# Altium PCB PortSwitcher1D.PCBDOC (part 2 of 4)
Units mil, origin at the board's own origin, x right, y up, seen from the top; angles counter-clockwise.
Board outline 6005.03 x 6005.03 mil, 4 copper layers (Top Layer, InternalPlane1, InternalPlane2, Bottom Layer); 153 components, 325 nets, 1175 pads, 173 vias.
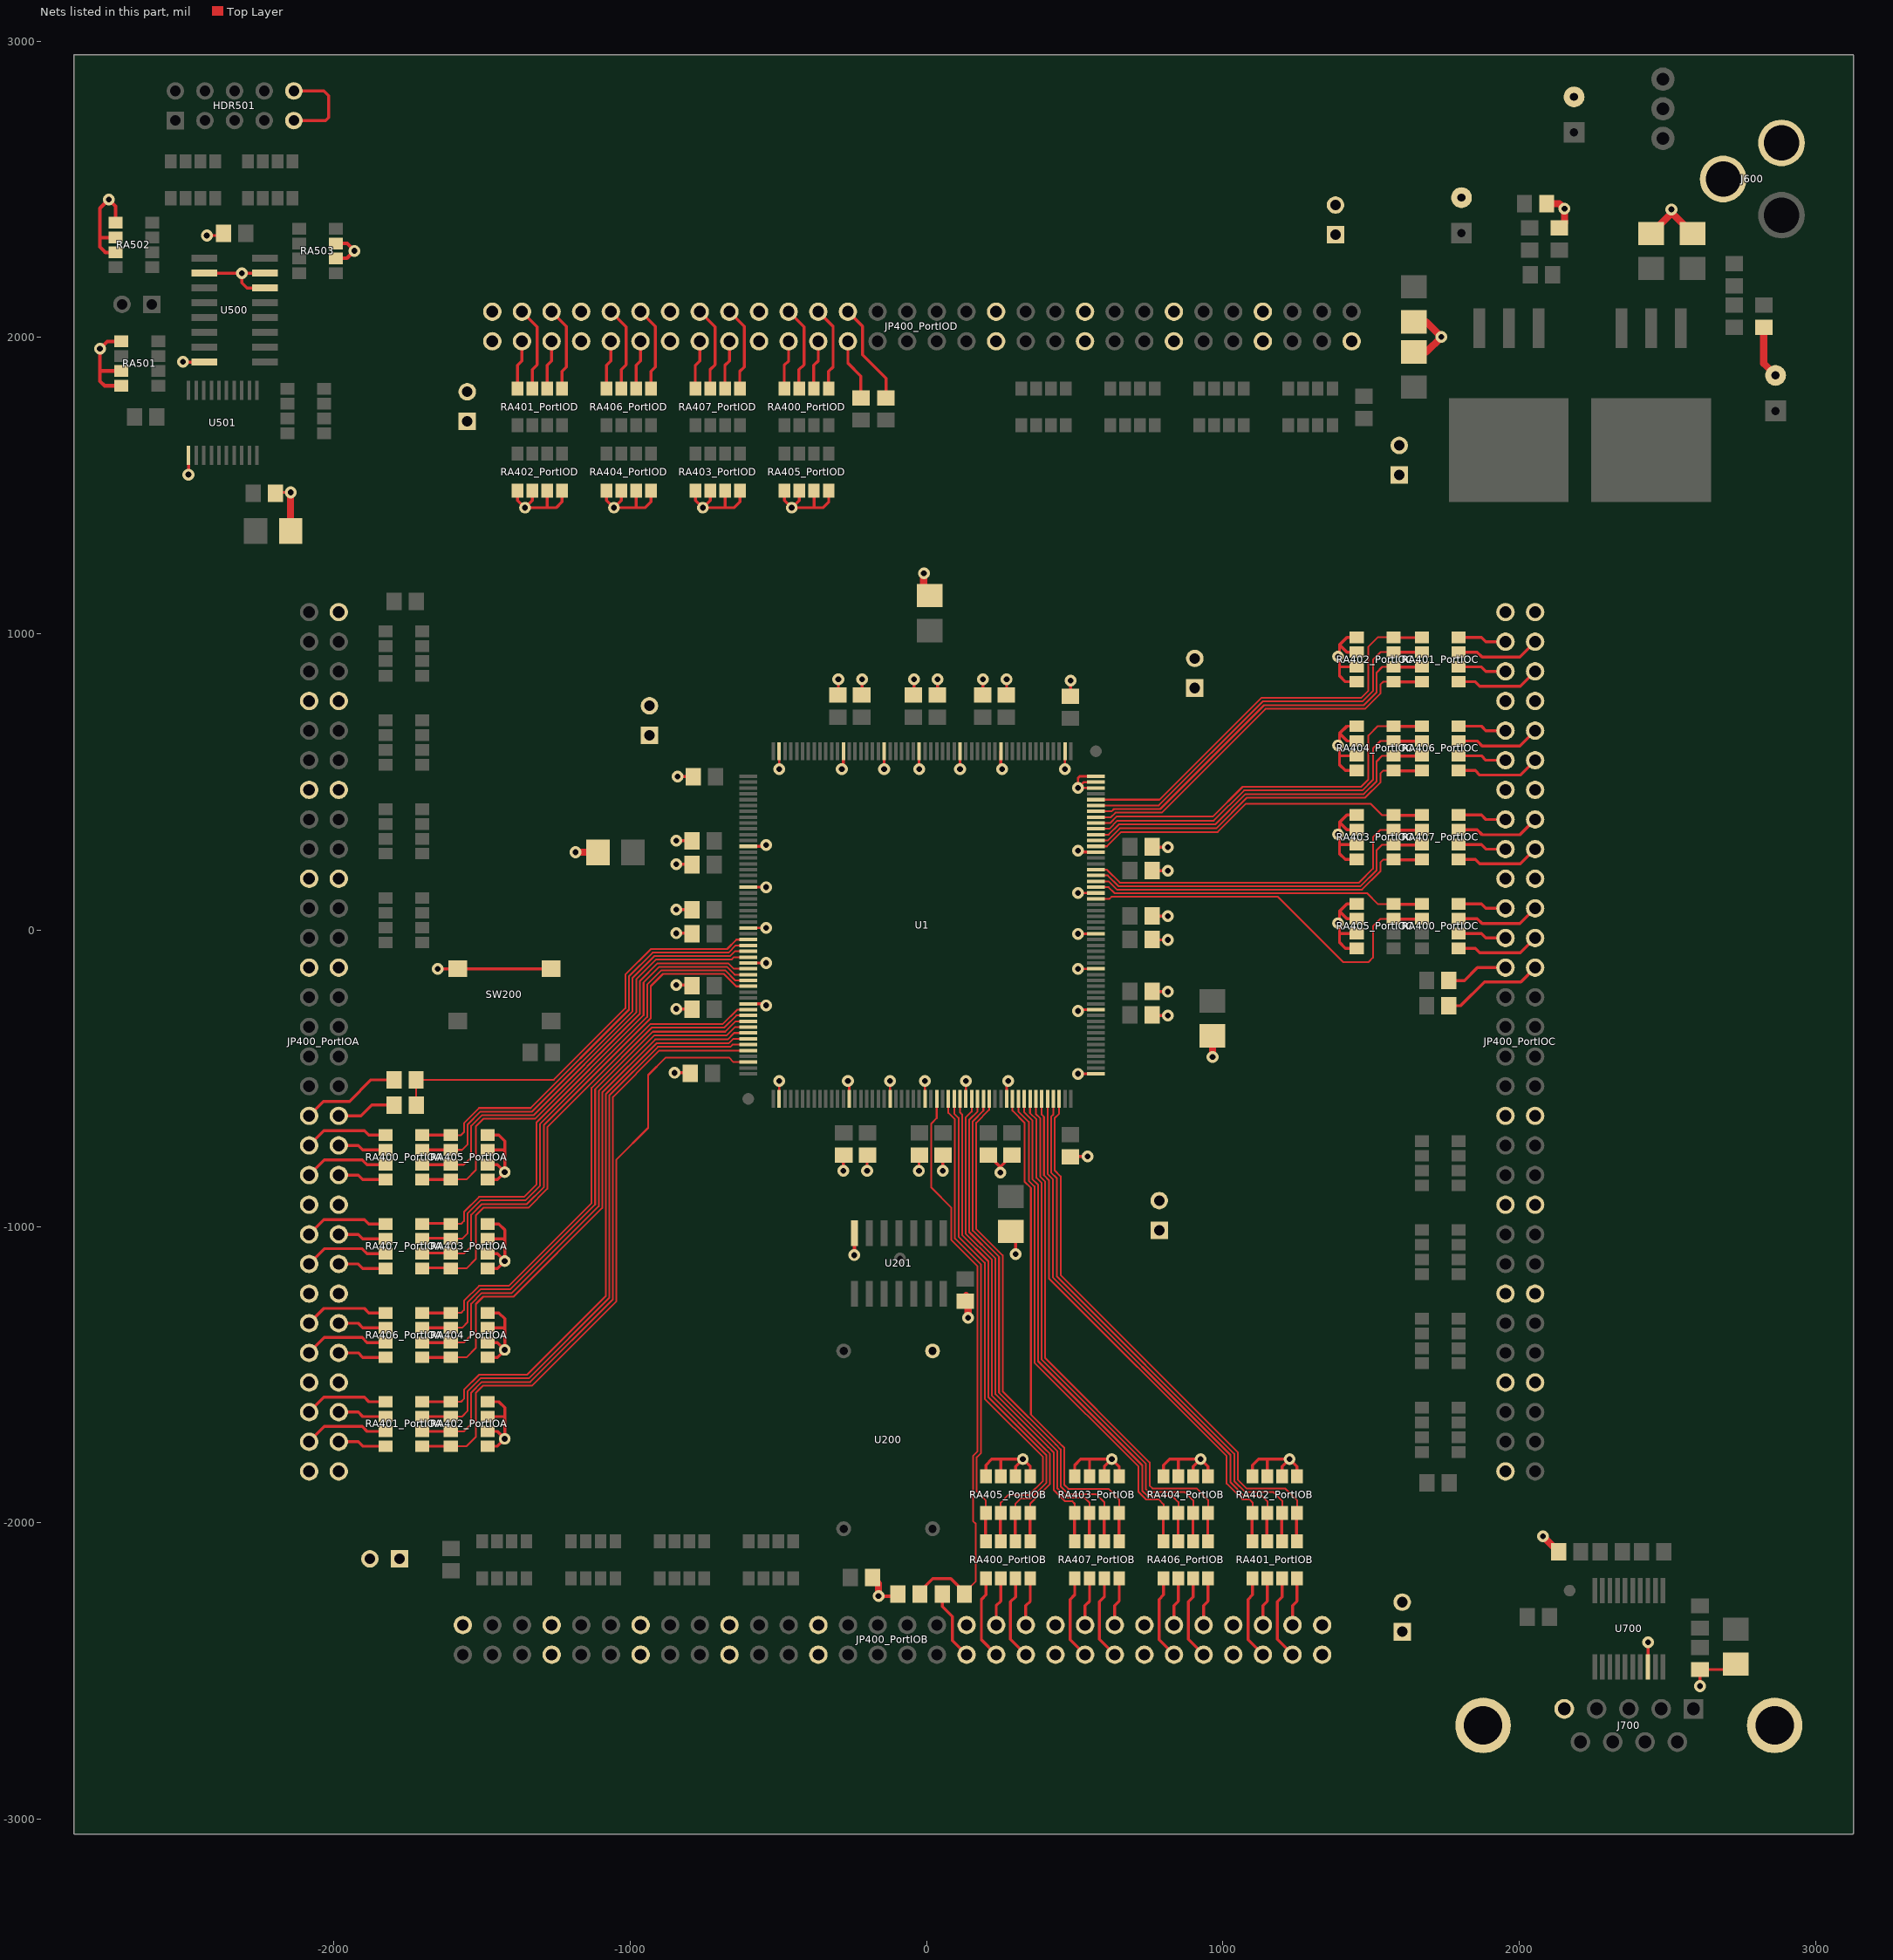
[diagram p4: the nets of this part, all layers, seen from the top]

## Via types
v1: diameter 40, hole 19.68, Top Layer to Bottom Layer, 173 vias

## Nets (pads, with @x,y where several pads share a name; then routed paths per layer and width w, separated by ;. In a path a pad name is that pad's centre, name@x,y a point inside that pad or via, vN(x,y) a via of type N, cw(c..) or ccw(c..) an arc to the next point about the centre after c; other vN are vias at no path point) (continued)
GND: C200.2 C201.2 C202.2 C203.2 C204.2 C205.2 C206.2 C207.2 C208.1 C209.1 C210.1 C211.1 C212.1 C213.1 C214.1 C215.1 C216.2 C217.2 C218.2 C219.2 C220.2 C221.2 C222.1 C223.1 C224.1 C225.1 C226.1 C227.1 C228.2 C229.2 C230.2 C231.2 C232.2 C233.2 C500.2 C501.2 C502.2 C600.2 C601.2 C602.2 C603.2 C604.2 C605.2 C606.2 C703.2 C704.2 C705.2 HDR501.9 HDR501.10 HDR600.1 HDR600.2 HDR601.1 HDR601.2 HDR602.1 HDR602.2 HDR603.1 HDR603.2 HDR604.1 HDR604.2 HDR605.1 HDR605.2 HDR606.1 HDR606.2 HDR607.1 HDR607.2 J600.2 J600.3 J700.5 J700.10 J700.11 JP400_PortIOA.1 JP400_PortIOA.2 JP400_PortIOA.7 JP400_PortIOA.8 JP400_PortIOA.13 JP400_PortIOA.14 JP400_PortIOA.19 JP400_PortIOA.20 JP400_PortIOA.26 JP400_PortIOA.35 JP400_PortIOA.36 JP400_PortIOA.41 JP400_PortIOA.42 JP400_PortIOA.47 JP400_PortIOA.48 JP400_PortIOA.53 JP400_PortIOA.54 JP400_PortIOA.60 JP400_PortIOB.1 JP400_PortIOB.2 JP400_PortIOB.7 JP400_PortIOB.8 JP400_PortIOB.13 JP400_PortIOB.14 JP400_PortIOB.19 JP400_PortIOB.20 JP400_PortIOB.26 JP400_PortIOB.35 JP400_PortIOB.36 JP400_PortIOB.41 JP400_PortIOB.42 JP400_PortIOB.47 JP400_PortIOB.48 JP400_PortIOB.53 JP400_PortIOB.54 JP400_PortIOB.60 JP400_PortIOC.1 JP400_PortIOC.2 JP400_PortIOC.7 JP400_PortIOC.8 JP400_PortIOC.13 JP400_PortIOC.14 JP400_PortIOC.19 JP400_PortIOC.20 JP400_PortIOC.26 JP400_PortIOC.35 JP400_PortIOC.36 JP400_PortIOC.41 JP400_PortIOC.42 JP400_PortIOC.47 JP400_PortIOC.48 JP400_PortIOC.53 JP400_PortIOC.54 JP400_PortIOC.60 JP400_PortIOD.1 JP400_PortIOD.2 JP400_PortIOD.7 JP400_PortIOD.8 JP400_PortIOD.13 JP400_PortIOD.14 JP400_PortIOD.19 JP400_PortIOD.20 JP400_PortIOD.26 JP400_PortIOD.35 JP400_PortIOD.36 JP400_PortIOD.41 JP400_PortIOD.42 JP400_PortIOD.47 JP400_PortIOD.48 JP400_PortIOD.53 JP400_PortIOD.54 JP400_PortIOD.60 pad.GND R401_PortIOA.1 R401_PortIOB.1 R401_PortIOC.1 R401_PortIOD.1 R603.1 R605.1 R606.1 RA402_PortIOA.1 RA402_PortIOA.2 RA402_PortIOA.3 RA402_PortIOA.4 RA402_PortIOB.1 RA402_PortIOB.2 RA402_PortIOB.3 RA402_PortIOB.4 RA402_PortIOC.1 RA402_PortIOC.2 RA402_PortIOC.3 RA402_PortIOC.4 RA402_PortIOD.1 RA402_PortIOD.2 RA402_PortIOD.3 RA402_PortIOD.4 RA403_PortIOA.1 RA403_PortIOA.2 RA403_PortIOA.3 RA403_PortIOA.4 RA403_PortIOB.1 RA403_PortIOB.2 RA403_PortIOB.3 RA403_PortIOB.4 RA403_PortIOC.1 RA403_PortIOC.2 RA403_PortIOC.3 RA403_PortIOC.4 RA403_PortIOD.1 RA403_PortIOD.2 RA403_PortIOD.3 RA403_PortIOD.4 RA404_PortIOA.1 RA404_PortIOA.2 RA404_PortIOA.3 RA404_PortIOA.4 RA404_PortIOB.1 RA404_PortIOB.2 RA404_PortIOB.3 RA404_PortIOB.4 RA404_PortIOC.1 RA404_PortIOC.2 RA404_PortIOC.3 RA404_PortIOC.4 RA404_PortIOD.1 RA404_PortIOD.2 RA404_PortIOD.3 RA404_PortIOD.4 RA405_PortIOA.1 RA405_PortIOA.2 RA405_PortIOA.3 RA405_PortIOA.4 RA405_PortIOB.1 RA405_PortIOB.2 RA405_PortIOB.3 RA405_PortIOB.4 RA405_PortIOC.1 RA405_PortIOC.2 RA405_PortIOC.3 RA405_PortIOC.4 RA405_PortIOD.1 RA405_PortIOD.2 RA405_PortIOD.3 RA405_PortIOD.4 RA501.5 RA501.7 RA501.8 RA502.5 RA502.6 RA502.7 RA503.6 RA503.7 SW200.3 SW200.4 U1.1 U1.12 U1.19 U1.25 U1.32 U1.39 U1.50 U1.51 U1.52 U1.54 U1.65 U1.72 U1.79 U1.85 U1.92 U1.103 U1.117 U1.124 U1.131 U1.137 U1.144 U1.158 U1.170 U1.177 U1.183 U1.190 U1.197 U200.7 U201.7 U500.2 U500.8 U500.14 U500.15 U501.11 U700.18 | length 20269.8
  Top Layer w8: v1(467.02,543.39) U1.54@467.02,603.91 ; 518.74,519.26 516.7,519.26 ; U1.50@571.35,479.89 v1(510.84,479.89) ; U1.51@571.35,499.58 530.52,499.58 ; U1.52@571.35,519.26 516.7,519.26 ; v1(510.84,479.89) 523.49,492.54 530.52,499.58 ; v1(510.84,479.89) 530.52,499.58 ; v1(510.84,479.89) 510.84,513.39 516.7,519.26 ; U1.137@-601.88,-110.66 v1(-541.37,-110.66) U1.137@-601.88,-110.66 ; U1.131@-601.88,7.45 v1(-541.37,7.45) U1.131@-601.88,7.45 ; U1.124@-601.88,145.24 v1(-541.37,145.24) U1.124@-601.88,145.24 ; U1.158@-497.55,-569.32 v1(-497.55,-508.81) U1.158@-497.55,-569.32 ; U1.103@-497.55,603.91 v1(-497.39,543.45) U1.103@-497.55,603.91 ; v1(-143.39,543.45) U1.85@-143.22,603.91 v1(-143.39,543.45) ; U1.177@-123.53,-569.32 v1(-123.53,-508.81) U1.177@-123.53,-569.32 ; v1(-25.39,543.45) U1.79@-25.11,603.91 v1(-25.39,543.45) ; U1.183@-5.42,-569.32 v1(-5.42,-508.81) U1.183@-5.42,-569.32 ; v1(112.69,543.39) U1.72@112.69,603.91 v1(112.69,543.39) ; U1.190@132.37,-569.32 v1(132.37,-508.81) U1.190@132.37,-569.32 ; v1(510.84,-484.68) U1.1@571.35,-484.68 v1(510.84,-484.68) ; v1(510.84,-130.35) U1.19@571.35,-130.35 v1(510.84,-130.35) ; v1(510.84,-12.24) U1.25@571.35,-12.24 v1(510.84,-12.24) ; v1(510.84,125.56) U1.32@571.35,125.56 v1(510.84,125.56)
  Top Layer w10: v1(-2509.7,1918.38) -2508.62,1917.29 U500.8@-2437.63,1917.29 ; v1(-2491.01,1537.57) -2490.42,1538.16 U501.11@-2490.42,1603.04 ; U500.2@-2437.63,2217.29 U500.15@-2232.9,2217.29 ; v1(-2429.02,2344.45) -2380.51,2344.45 C501.2@-2372.67,2352.29 ; v1(-2310.94,2217.29) -2310.94,2185.04 -2293.18,2167.29 U500.14@-2232.9,2167.29 ; C500.2@-2195.4,1477.55 v1(-2145.62,1477.55) ; HDR501.9@-2135.26,2732.29 -2028.38,2732.29 -2017.7,2742.97 -2017.7,2815.79 -2034.21,2832.29 HDR501.10@-2135.26,2832.29 ; JP400_PortIOA.26@-1983.77,-626.41 -1908.56,-626.41 -1872.15,-590 R401_PortIOA.1@-1797.4,-590 ; v1(-1649.69,-130.31) -1268.18,-130.31 SW200.3@-1267.39,-129.52 ; v1(-850.34,-481.44) C208.1@-798.93,-481.44 ; v1(-844.34,-265.44) C213.1@-792.93,-265.44 ; v1(-844.34,-185.44) C226.1@-792.93,-185.44 ; v1(-844.34,-10.44) C212.1@-792.93,-10.44 ; v1(-844.34,69.56) C225.1@-792.93,69.56 ; v1(-844.34,222.56) C221.2@-792.93,222.56 ; v1(-844.34,302.56) C207.2@-792.93,302.56 ; v1(-840.34,518.56) C204.2@-788.93,518.56 ; C201.2@-298,794.96 v1(-298,846.37) ; v1(-280.85,-811.79) C206.2@-280.85,-760.38 ; JP400_PortIOD.26@-265.66,1987.37 -265.66,1913.86 -222.07,1870.27 R401_PortIOD.1@-222.07,1796.53 ; C220.2@-218,794.96 v1(-218,846.37) ; v1(-200.85,-811.79) C218.2@-200.85,-760.38 ; C200.2@-43,794.96 v1(-43,846.37) ; v1(-25.85,-811.79) C211.1@-25.85,-760.38 ; C219.2@37,794.96 v1(37,846.37) ; v1(54.15,-811.79) C227.1@54.15,-760.38 ; C224.1@190,794.96 v1(190,846.37) ; C217.2@208.42,-759.11 v1@248.78,-799.46 ; v1(248.78,-817.53) 248.78,-798.76 C214.1@288.42,-759.11 ; C203.2@270,794.96 v1(270,846.37) ; C231.2@284.74,-1016.76 300.68,-1032.71 v1(300.68,-1092.94) ; C215.1@484.74,-765.11 486.63,-763.22 v1(542.81,-763.22) ; C202.2@486,790.96 v1(486,842.37) ; C205.2@762.41,-287.66 v1(813.82,-287.66) ; C216.2@762.41,-207.66 v1(813.82,-207.66) ; C210.1@762.41,-32.66 v1(813.82,-32.66) ; C222.1@762.41,47.34 v1(813.82,47.34) ; C223.1@762.41,200.34 v1(813.82,200.34) ; C209.1@762.41,280.34 v1(813.82,280.34) ; R401_PortIOC.1@1762.4,-170 1814.73,-170 1858.32,-126.41 JP400_PortIOC.26@1953.24,-126.41 ; U700.18@2434.9,-2485.46 v1(2434.9,-2403.35) ; v1@2609.74,-2550.64 C704.2@2609.74,-2495.11 2711.39,-2495.11 C705.2@2729.74,-2476.76 ; -1448.77,-1741.41 RA402_PortIOA.1@-1481.77,-1741.41 -1448.77,-1741.41 ; -1448.77,-1741.41 pad.GND@-1423.77,-1716.41 ; -1448.77,-1741.41 pad.GND@-1423.77,-1716.41 ; -1448.77,-1691.41 RA402_PortIOA.2@-1481.77,-1691.41 -1448.77,-1691.41 ; -1448.77,-1691.41 pad.GND@-1423.77,-1716.41 ; -1448.77,-1691.41 pad.GND@-1423.77,-1716.41 ; -1448.77,-1441.41 RA404_PortIOA.1@-1481.77,-1441.41 -1448.77,-1441.41 ; -1448.77,-1441.41 pad.GND@-1423.77,-1416.41 ; -1448.77,-1441.41 pad.GND@-1423.77,-1416.41 ; -1448.77,-1391.41 pad.GND@-1423.77,-1416.41 ; -1448.77,-1391.41 RA404_PortIOA.2@-1481.77,-1391.41 -1448.77,-1391.41 ; -1448.77,-1391.41 pad.GND@-1423.77,-1416.41 ; -1448.77,-1141.41 RA403_PortIOA.1@-1481.77,-1141.41 -1448.77,-1141.41 ; -1448.77,-1141.41 pad.GND@-1423.77,-1116.41 ; -1448.77,-1141.41 pad.GND@-1423.77,-1116.41 ; -1448.77,-1091.41 RA403_PortIOA.2@-1481.77,-1091.41 -1448.77,-1091.41 ; -1448.77,-1091.41 pad.GND@-1423.77,-1116.41 ; -1448.77,-1091.41 pad.GND@-1423.77,-1116.41 ; -1448.77,-841.41 RA405_PortIOA.1@-1481.77,-841.41 -1448.77,-841.41 ; -1448.77,-841.41 pad.GND@-1423.77,-816.41 ; -1448.77,-841.41 pad.GND@-1423.77,-816.41 ; -1448.77,-791.41 RA405_PortIOA.2@-1481.77,-791.41 -1448.77,-791.41 ; -1448.77,-791.41 pad.GND@-1423.77,-816.41 ; -1448.77,-791.41 pad.GND@-1423.77,-816.41 ; -1443.77,-1591.41 -1423.77,-1611.41 ; -1443.77,-1591.41 RA402_PortIOA.4@-1481.77,-1591.41 -1443.77,-1591.41 ; -1443.77,-1291.41 -1423.77,-1311.41 ; -1443.77,-1291.41 RA404_PortIOA.4@-1481.77,-1291.41 -1443.77,-1291.41 ; -1443.77,-991.41 -1423.77,-1011.41 ; -1443.77,-991.41 RA403_PortIOA.4@-1481.77,-991.41 -1443.77,-991.41 ; -1443.77,-691.41 -1423.77,-711.41 ; -1443.77,-691.41 RA405_PortIOA.4@-1481.77,-691.41 -1443.77,-691.41 ; pad.GND@-1423.77,-1716.41 -1423.77,-1641.41 ; pad.GND@-1423.77,-1716.41 -1423.77,-1641.41 ; -1423.77,-1641.41 RA402_PortIOA.3@-1481.77,-1641.41 -1423.77,-1641.41 ; -1423.77,-1641.41 -1423.77,-1611.41 ; -1423.77,-1641.41 -1423.77,-1611.41 ; pad.GND@-1423.77,-1416.41 -1423.77,-1341.41 ; pad.GND@-1423.77,-1416.41 -1423.77,-1341.41 ; -1423.77,-1341.41 -1423.77,-1311.41 ; -1423.77,-1341.41 RA404_PortIOA.3@-1481.77,-1341.41 -1423.77,-1341.41 ; -1423.77,-1341.41 -1423.77,-1311.41 ; pad.GND@-1423.77,-1116.41 -1423.77,-1041.41 ; pad.GND@-1423.77,-1116.41 -1423.77,-1041.41 ; -1423.77,-1041.41 RA403_PortIOA.3@-1481.77,-1041.41 -1423.77,-1041.41 ; -1423.77,-1041.41 -1423.77,-1011.41 ; -1423.77,-1041.41 -1423.77,-1011.41 ; pad.GND@-1423.77,-816.41 -1423.77,-741.41 ; pad.GND@-1423.77,-816.41 -1423.77,-741.41 ; -1423.77,-741.41 RA405_PortIOA.3@-1481.77,-741.41 -1423.77,-741.41 ; -1423.77,-741.41 -1423.77,-711.41 ; -1423.77,-741.41 -1423.77,-711.41 ; -1380.26,1450.8 pad.GND@-1355.26,1425.8 ; -1380.26,1450.8 RA402_PortIOD.1@-1380.26,1483.8 -1380.26,1450.8 ; -1380.26,1450.8 pad.GND@-1355.26,1425.8 ; pad.GND@-1355.26,1425.8 -1280.26,1425.8 ; pad.GND@-1355.26,1425.8 -1330.26,1450.8 ; pad.GND@-1355.26,1425.8 -1330.26,1450.8 ; pad.GND@-1355.26,1425.8 -1280.26,1425.8 ; -1330.26,1450.8 RA402_PortIOD.2@-1330.26,1483.8 -1330.26,1450.8 ; -1280.26,1425.8 -1250.26,1425.8 ; -1280.26,1425.8 RA402_PortIOD.3@-1280.26,1483.8 -1280.26,1425.8 ; -1280.26,1425.8 -1250.26,1425.8 ; -1250.26,1425.8 -1230.26,1445.8 ; -1230.26,1445.8 RA402_PortIOD.4@-1230.26,1483.8 -1230.26,1445.8 ; -1080.26,1450.8 RA404_PortIOD.1@-1080.26,1483.8 -1080.26,1450.8 ; -1080.26,1450.8 pad.GND@-1055.26,1425.8 ; -1080.26,1450.8 pad.GND@-1055.26,1425.8 ; pad.GND@-1055.26,1425.8 -980.26,1425.8 ; pad.GND@-1055.26,1425.8 -1030.26,1450.8 ; pad.GND@-1055.26,1425.8 -1030.26,1450.8 ; pad.GND@-1055.26,1425.8 -980.26,1425.8 ; -1030.26,1450.8 RA404_PortIOD.2@-1030.26,1483.8 -1030.26,1450.8 ; -980.26,1425.8 -950.26,1425.8 ; -980.26,1425.8 RA404_PortIOD.3@-980.26,1483.8 -980.26,1425.8 ; -980.26,1425.8 -950.26,1425.8 ; -950.26,1425.8 -930.26,1445.8 ; -930.26,1445.8 RA404_PortIOD.4@-930.26,1483.8 -930.26,1445.8 ; -780.26,1450.8 pad.GND@-755.26,1425.8 ; -780.26,1450.8 RA403_PortIOD.1@-780.26,1483.8 -780.26,1450.8 ; -780.26,1450.8 pad.GND@-755.26,1425.8 ; pad.GND@-755.26,1425.8 -680.26,1425.8 ; pad.GND@-755.26,1425.8 -730.26,1450.8 ; pad.GND@-755.26,1425.8 -730.26,1450.8 ; pad.GND@-755.26,1425.8 -680.26,1425.8 ; -730.26,1450.8 RA403_PortIOD.2@-730.26,1483.8 -730.26,1450.8 ; -680.26,1425.8 -650.26,1425.8 ; -680.26,1425.8 RA403_PortIOD.3@-680.26,1483.8 -680.26,1425.8 ; -680.26,1425.8 -650.26,1425.8 ; -650.26,1425.8 -630.26,1445.8 ; -630.26,1445.8 RA403_PortIOD.4@-630.26,1483.8 -630.26,1445.8 ; v1@-546.61,-248.46 U1.144@-601.88,-248.46 v1@-546.61,-248.46 ; v1@-546.61,-248.46 v1(-541.39,-253.68) v1@-546.61,-248.46 ; v1@-545.8,283.04 U1.117@-601.88,283.04 v1@-545.8,283.04 ; v1@-545.8,283.04 v1(-541.39,287.45) v1@-545.8,283.04 ; -480.26,1450.8 pad.GND@-455.26,1425.8 ; -480.26,1450.8 RA405_PortIOD.1@-480.26,1483.8 -480.26,1450.8 ; -480.26,1450.8 pad.GND@-455.26,1425.8 ; pad.GND@-455.26,1425.8 -380.26,1425.8 ; pad.GND@-455.26,1425.8 -430.26,1450.8 ; pad.GND@-455.26,1425.8 -430.26,1450.8 ; pad.GND@-455.26,1425.8 -380.26,1425.8 ; -430.26,1450.8 RA405_PortIOD.2@-430.26,1483.8 -430.26,1450.8 ; -380.26,1425.8 -350.26,1425.8 ; -380.26,1425.8 RA405_PortIOD.3@-380.26,1483.8 -380.26,1425.8 ; -380.26,1425.8 -350.26,1425.8 ; -350.26,1425.8 -330.26,1445.8 ; -330.26,1445.8 RA405_PortIOD.4@-330.26,1483.8 -330.26,1445.8 ; v1@-281.01,548.64 v1(-286.23,543.42) v1@-281.01,548.64 ; v1@-281.01,548.64 U1.92@-281.01,603.91 v1@-281.01,548.64 ; v1@-261.33,-513.24 v1(-265.74,-508.83) v1@-261.33,-513.24 ; v1@-261.33,-513.24 U1.170@-261.33,-569.32 v1@-261.33,-513.24 ; 199.74,-1804.91 219.74,-1784.91 ; 199.74,-1804.91 RA405_PortIOB.4@199.74,-1842.91 199.74,-1804.91 ; 219.74,-1784.91 249.74,-1784.91 ; 219.74,-1784.91 249.74,-1784.91 ; 249.74,-1784.91 pad.GND@324.74,-1784.91 ; 249.74,-1784.91 RA405_PortIOB.3@249.74,-1842.91 249.74,-1784.91 ; 249.74,-1784.91 pad.GND@324.74,-1784.91 ; v1@250.48,547.83 v1(254.89,543.42) v1@250.48,547.83 ; v1@250.48,547.83 U1.65@250.48,603.91 v1@250.48,547.83 ; v1@270.17,-514.05 U1.197@270.17,-569.32 v1@270.17,-514.05 ; v1@270.17,-514.05 v1(275.39,-508.83) v1@270.17,-514.05 ; 299.74,-1809.91 RA405_PortIOB.2@299.74,-1842.91 299.74,-1809.91 ; 299.74,-1809.91 pad.GND@324.74,-1784.91 ; 299.74,-1809.91 pad.GND@324.74,-1784.91 ; pad.GND@324.74,-1784.91 349.74,-1809.91 ; pad.GND@324.74,-1784.91 349.74,-1809.91 ; 349.74,-1809.91 RA405_PortIOB.1@349.74,-1842.91 349.74,-1809.91 ; 499.74,-1804.91 519.74,-1784.91 ; 499.74,-1804.91 RA403_PortIOB.4@499.74,-1842.91 499.74,-1804.91 ; v1@515.27,-268.14 v1(510.86,-272.55) v1@515.27,-268.14 ; v1@515.27,-268.14 U1.12@571.35,-268.14 v1@515.27,-268.14 ; v1@516.08,263.35 v1(510.86,268.57) v1@516.08,263.35 ; v1@516.08,263.35 U1.39@571.35,263.35 v1@516.08,263.35 ; 519.74,-1784.91 549.74,-1784.91 ; 519.74,-1784.91 549.74,-1784.91 ; 549.74,-1784.91 RA403_PortIOB.3@549.74,-1842.91 549.74,-1784.91 ; 549.74,-1784.91 pad.GND@624.74,-1784.91 ; 549.74,-1784.91 pad.GND@624.74,-1784.91 ; 599.74,-1809.91 RA403_PortIOB.2@599.74,-1842.91 599.74,-1809.91 ; 599.74,-1809.91 pad.GND@624.74,-1784.91 ; 599.74,-1809.91 pad.GND@624.74,-1784.91 ; pad.GND@624.74,-1784.91 649.74,-1809.91 ; pad.GND@624.74,-1784.91 649.74,-1809.91 ; 649.74,-1809.91 RA403_PortIOB.1@649.74,-1842.91 649.74,-1809.91 ; 799.74,-1804.91 819.74,-1784.91 ; 799.74,-1804.91 RA404_PortIOB.4@799.74,-1842.91 799.74,-1804.91 ; 819.74,-1784.91 849.74,-1784.91 ; 819.74,-1784.91 849.74,-1784.91 ; 849.74,-1784.91 RA404_PortIOB.3@849.74,-1842.91 849.74,-1784.91 ; 849.74,-1784.91 pad.GND@924.74,-1784.91 ; 849.74,-1784.91 pad.GND@924.74,-1784.91 ; 899.74,-1809.91 RA404_PortIOB.2@899.74,-1842.91 899.74,-1809.91 ; 899.74,-1809.91 pad.GND@924.74,-1784.91 ; 899.74,-1809.91 pad.GND@924.74,-1784.91 ; pad.GND@924.74,-1784.91 949.74,-1809.91 ; pad.GND@924.74,-1784.91 949.74,-1809.91 ; 949.74,-1809.91 RA404_PortIOB.1@949.74,-1842.91 949.74,-1809.91 ; 1099.74,-1804.91 1119.74,-1784.91 ; 1099.74,-1804.91 RA402_PortIOB.4@1099.74,-1842.91 1099.74,-1804.91 ; 1119.74,-1784.91 1149.74,-1784.91 ; 1119.74,-1784.91 1149.74,-1784.91 ; 1149.74,-1784.91 pad.GND@1224.74,-1784.91 ; 1149.74,-1784.91 RA402_PortIOB.3@1149.74,-1842.91 1149.74,-1784.91 ; 1149.74,-1784.91 pad.GND@1224.74,-1784.91 ; 1199.74,-1809.91 RA402_PortIOB.2@1199.74,-1842.91 1199.74,-1809.91 ; 1199.74,-1809.91 pad.GND@1224.74,-1784.91 ; 1199.74,-1809.91 pad.GND@1224.74,-1784.91 ; pad.GND@1224.74,-1784.91 1249.74,-1809.91 ; pad.GND@1224.74,-1784.91 1249.74,-1809.91 ; 1249.74,-1809.91 RA402_PortIOB.1@1249.74,-1842.91 1249.74,-1809.91 ; 1393.24,-41.41 1413.24,-61.41 ; 1393.24,-41.41 1393.24,-11.41 ; 1393.24,-41.41 pad.GND@1393.24,23.59 ; 1393.24,-41.41 1393.24,-11.41 ; 1393.24,-11.41 pad.GND@1393.24,23.59 ; 1393.24,-11.41 RA405_PortIOC.3@1451.24,-11.41 1393.24,-11.41 ; pad.GND@1393.24,23.59 1393.24,63.59 ; pad.GND@1393.24,23.59 1393.24,63.59 ; 1393.24,63.59 1418.24,38.59 ; 1393.24,63.59 1405.84,76.19 1418.24,88.59 ; 1393.24,258.59 1413.24,238.59 ; 1393.24,258.59 1393.24,288.59 ; 1393.24,258.59 pad.GND@1393.24,323.59 ; 1393.24,258.59 1393.24,288.59 ; 1393.24,288.59 pad.GND@1393.24,323.59 ; 1393.24,288.59 1431.94,288.59 RA403_PortIOC.3@1451.24,288.59 1393.24,288.59 ; pad.GND@1393.24,323.59 1393.24,327.29 1393.24,330.29 1393.24,363.59 ; pad.GND@1393.24,323.59 1393.24,363.59 ; 1393.24,363.59 1418.24,388.59 ; 1393.24,363.59 1418.24,338.59 ; 1393.24,558.59 1413.24,538.59 ; 1393.24,558.59 1393.24,588.59 ; 1393.24,558.59 pad.GND@1393.24,623.59 ; 1393.24,558.59 1393.24,588.59 ; 1393.24,588.59 1393.24,622.79 pad.GND@1393.24,623.59 ; 1393.24,588.59 1427.44,588.59 RA404_PortIOC.3@1451.24,588.59 1393.24,588.59 ; pad.GND@1393.24,623.59 1393.24,663.59 ; pad.GND@1393.24,623.59 1393.24,663.59 ; 1393.24,663.59 1418.24,688.59 ; 1393.24,663.59 1418.24,638.59 ; 1393.24,858.59 1413.24,838.59 ; 1393.24,858.59 1393.24,888.59 ; 1393.24,858.59 pad.GND@1393.24,923.59 ; 1393.24,858.59 1393.24,888.59 ; 1393.24,888.59 pad.GND@1393.24,923.59 ; 1393.24,888.59 RA402_PortIOC.3@1451.24,888.59 1393.24,888.59 ; pad.GND@1393.24,923.59 1393.24,963.59 ; pad.GND@1393.24,923.59 1393.24,963.59 ; 1393.24,963.59 1418.24,988.59 ; 1393.24,963.59 1418.24,938.59 ; 1413.24,-61.41 RA405_PortIOC.4@1451.24,-61.41 1413.24,-61.41 ; 1413.24,238.59 RA403_PortIOC.4@1451.24,238.59 1413.24,238.59 ; 1413.24,538.59 RA404_PortIOC.4@1451.24,538.59 1413.24,538.59 ; 1413.24,838.59 RA402_PortIOC.4@1451.24,838.59 1413.24,838.59 ; 1418.24,38.59 1443.44,38.59 RA405_PortIOC.2@1451.24,38.59 1418.24,38.59 ; 1418.24,88.59 RA405_PortIOC.1@1451.24,88.59 1418.24,88.59 ; 1418.24,338.59 RA403_PortIOC.2@1451.24,338.59 1418.24,338.59 ; 1418.24,388.59 1426.74,388.59 RA403_PortIOC.1@1451.24,388.59 1418.24,388.59 ; 1418.24,638.59 RA404_PortIOC.2@1451.24,638.59 1418.24,638.59 ; 1418.24,688.59 RA404_PortIOC.1@1451.24,688.59 1418.24,688.59 ; 1418.24,938.59 RA402_PortIOC.2@1451.24,938.59 1418.24,938.59 ; 1418.24,988.59 RA402_PortIOC.1@1451.24,988.59 1418.24,988.59
  Top Layer w12: -2789.35,2337.29 RA502.6@-2737.26,2337.29 ; -2788.64,1887.29 RA501.7@-2717.26,1887.29 ; RA502.7@-2737.26,2287.29 -2771.42,2287.29 -2789.64,2305.51 -2789.64,2436.38 v1(-2760.12,2465.9) -2737.26,2443.05 RA502.5@-2737.26,2387.29 ; RA501.8@-2717.26,1837.29 -2774.06,1837.29 -2789.64,1852.87 v1(-2789.64,1962.1) -2764.44,1987.29 RA501.5@-2717.26,1987.29 ; RA503.6@-1993.26,2267.29 -1956.04,2267.29 v1(-1930.61,2292.72) -1955.18,2317.29 RA503.7@-1993.26,2317.29 ; v1@-244,-1096.06 U201.7@-244,-1022.08 ; v1(-162.36,-2247.46) -104.86,-2247.46 R401_PortIOB.1@-97.4,-2240
  Top Layer w24: C502.2@-2146.21,1347.29 -2146.21,1476.96 v1(-2145.62,1477.55) ; v1(-1185.24,263.29) C228.2@-1110.32,263.29 ; C232.2@-182.6,-2185 -162.36,-2205.24 v1(-162.36,-2247.46) ; C230.2@-10.26,1131.35 -10.26,1203.09 v1(-9.36,1204) ; C233.2@130,-1252.4 139.73,-1262.13 v1(139.73,-1307.74) ; C233.2@133.12,-1233.14 C233.2@143.2,-1243.22 ; C229.2@964.74,-356.76 964.8,-356.83 v1(964.8,-427.48) ; C603.2@1644.74,1951.35 1686.57,1951.35 v1(1737.24,2002.02) 1686.02,2053.24 C600.2@1644.74,2053.24 ; v1(2080.18,-2045.74) 2080.36,-2045.74 C703.2@2132.33,-2097.71 ; R606.1@2092.14,2452.29 2135.18,2452.29 v1(2152.49,2434.98) 2152.49,2387.45 R605.1@2134.74,2369.69 ; C602.2@2444.74,2351.35 2513.14,2419.75 v1(2513.14,2432.45) ; v1@2513.14,2422.95 C601.2@2584.74,2351.35 ; R603.1@2824.74,2034.89 2824.74,1912.29 C604.2@2864.74,1872.29
  other v1: 2610.05,-2550.95 -244.54,-1096.6
I0_PortIOA: JP400_PortIOA.4 RA401_PortIOA.4 | length 164.2
  Top Layer w10: JP400_PortIOA.4@-1983.77,-1726.41 -1918.02,-1726.41 -1903.02,-1741.41 RA401_PortIOA.4@-1825.77,-1741.41
I0_PortIOB: JP400_PortIOB.4 RA401_PortIOB.4 | length 164.2
  Top Layer w10: JP400_PortIOB.4@1234.74,-2344.91 1234.74,-2279.17 1249.74,-2264.17 RA401_PortIOB.4@1249.74,-2186.91
I0_PortIOC: JP400_PortIOC.4 RA401_PortIOC.4 | length 164.2
  Top Layer w10: RA401_PortIOC.4@1795.24,988.59 1872.49,988.59 1887.49,973.59 JP400_PortIOC.4@1953.24,973.59
I0_PortIOD: JP400_PortIOD.4 RA401_PortIOD.4 | length 164.2
  Top Layer w10: RA401_PortIOD.4@-1380.66,1829.37 -1380.66,1906.62 -1365.66,1921.62 JP400_PortIOD.4@-1365.66,1987.37
I1_PortIOA: JP400_PortIOA.3 RA401_PortIOA.3 | length 286.2
  Top Layer w10: JP400_PortIOA.3@-2083.77,-1726.41 -2032.19,-1674.83 -1905.03,-1674.83 -1888.45,-1691.41 RA401_PortIOA.3@-1825.77,-1691.41
I1_PortIOB: JP400_PortIOB.3 RA401_PortIOB.3 | length 286.2
  Top Layer w10: RA401_PortIOB.3@1199.74,-2186.91 1199.74,-2249.6 1183.16,-2266.17 1183.16,-2393.34 JP400_PortIOB.3@1234.74,-2444.91
I1_PortIOC: JP400_PortIOC.3 RA401_PortIOC.3 | length 286.2
  Top Layer w10: RA401_PortIOC.3@1795.24,938.59 1857.93,938.59 1874.5,922.02 2001.66,922.02 JP400_PortIOC.3@2053.24,973.59
I1_PortIOD: JP400_PortIOD.3 RA401_PortIOD.3 | length 286.2
  Top Layer w10: JP400_PortIOD.3@-1365.66,2087.37 -1314.08,2035.8 -1314.08,1908.63 -1330.66,1892.06 RA401_PortIOD.3@-1330.66,1829.37
I2_PortIOA: JP400_PortIOA.6 RA401_PortIOA.2 | length 164.2
  Top Layer w10: JP400_PortIOA.6@-1983.77,-1626.41 -1918.02,-1626.41 -1903.02,-1641.41 RA401_PortIOA.2@-1825.77,-1641.41
I2_PortIOB: JP400_PortIOB.6 RA401_PortIOB.2 | length 164.2
  Top Layer w10: JP400_PortIOB.6@1134.74,-2344.91 1134.74,-2279.17 1149.74,-2264.17 RA401_PortIOB.2@1149.74,-2186.91
I2_PortIOC: JP400_PortIOC.6 RA401_PortIOC.2 | length 164.2
  Top Layer w10: RA401_PortIOC.2@1795.24,888.59 1872.49,888.59 1887.49,873.59 JP400_PortIOC.6@1953.24,873.59
I2_PortIOD: JP400_PortIOD.6 RA401_PortIOD.2 | length 164.2
  Top Layer w10: RA401_PortIOD.2@-1280.66,1829.37 -1280.66,1906.62 -1265.66,1921.62 JP400_PortIOD.6@-1265.66,1987.37
I3_PortIOA: JP400_PortIOA.5 RA401_PortIOA.1 | length 284.9
  Top Layer w10: JP400_PortIOA.5@-2083.77,-1626.41 -2033.77,-1576.41 -1897.16,-1576.41 -1882.16,-1591.41 RA401_PortIOA.1@-1825.77,-1591.41
I3_PortIOB: JP400_PortIOB.5 RA401_PortIOB.1 | length 284.9
  Top Layer w10: RA401_PortIOB.1@1099.74,-2186.91 1099.74,-2243.3 1084.74,-2258.3 1084.74,-2394.91 JP400_PortIOB.5@1134.74,-2444.91
I3_PortIOC: JP400_PortIOC.5 RA401_PortIOC.1 | length 284.9
  Top Layer w10: RA401_PortIOC.1@1795.24,838.59 1851.63,838.59 1866.63,823.59 2003.24,823.59 JP400_PortIOC.5@2053.24,873.59
I3_PortIOD: JP400_PortIOD.5 RA401_PortIOD.1 | length 284.9
  Top Layer w10: JP400_PortIOD.5@-1265.66,2087.37 -1215.66,2037.37 -1215.66,1900.76 -1230.66,1885.76 RA401_PortIOD.1@-1230.66,1829.37
I4_PortIOA: JP400_PortIOA.10 RA406_PortIOA.4 | length 164.2
  Top Layer w10: JP400_PortIOA.10@-1983.77,-1426.41 -1918.02,-1426.41 -1903.02,-1441.41 RA406_PortIOA.4@-1825.77,-1441.41
I4_PortIOB: JP400_PortIOB.10 RA406_PortIOB.4 | length 164.2
  Top Layer w10: JP400_PortIOB.10@934.74,-2344.91 934.74,-2279.17 949.74,-2264.17 RA406_PortIOB.4@949.74,-2186.91
I4_PortIOC: JP400_PortIOC.10 RA406_PortIOC.4 | length 164.2
  Top Layer w10: RA406_PortIOC.4@1795.24,688.59 1872.49,688.59 1887.49,673.59 JP400_PortIOC.10@1953.24,673.59
I4_PortIOD: JP400_PortIOD.10 RA406_PortIOD.4 | length 164.2
  Top Layer w10: RA406_PortIOD.4@-1080.66,1829.37 -1080.66,1906.62 -1065.66,1921.62 JP400_PortIOD.10@-1065.66,1987.37
I5_PortIOA: JP400_PortIOA.9 RA406_PortIOA.3 | length 286.2
  Top Layer w10: JP400_PortIOA.9@-2083.77,-1426.41 -2032.19,-1374.83 -1905.03,-1374.83 -1888.45,-1391.41 RA406_PortIOA.3@-1825.77,-1391.41
I5_PortIOB: JP400_PortIOB.9 RA406_PortIOB.3 | length 286.2
  Top Layer w10: RA406_PortIOB.3@899.74,-2186.91 899.74,-2249.6 883.16,-2266.17 883.16,-2393.34 JP400_PortIOB.9@934.74,-2444.91
I5_PortIOC: JP400_PortIOC.9 RA406_PortIOC.3 | length 286.2
  Top Layer w10: RA406_PortIOC.3@1795.24,638.59 1857.93,638.59 1874.5,622.02 2001.66,622.02 JP400_PortIOC.9@2053.24,673.59
I5_PortIOD: JP400_PortIOD.9 RA406_PortIOD.3 | length 286.2
  Top Layer w10: JP400_PortIOD.9@-1065.66,2087.37 -1014.08,2035.8 -1014.08,1908.63 -1030.66,1892.06 RA406_PortIOD.3@-1030.66,1829.37
I6_PortIOA: JP400_PortIOA.12 RA406_PortIOA.2 | length 164.2
  Top Layer w10: JP400_PortIOA.12@-1983.77,-1326.41 -1918.02,-1326.41 -1903.02,-1341.41 RA406_PortIOA.2@-1825.77,-1341.41
I6_PortIOB: JP400_PortIOB.12 RA406_PortIOB.2 | length 164.2
  Top Layer w10: JP400_PortIOB.12@834.74,-2344.91 834.74,-2279.17 849.74,-2264.17 RA406_PortIOB.2@849.74,-2186.91
I6_PortIOC: JP400_PortIOC.12 RA406_PortIOC.2 | length 164.2
  Top Layer w10: RA406_PortIOC.2@1795.24,588.59 1872.49,588.59 1887.49,573.59 JP400_PortIOC.12@1953.24,573.59
I6_PortIOD: JP400_PortIOD.12 RA406_PortIOD.2 | length 164.2
  Top Layer w10: RA406_PortIOD.2@-980.66,1829.37 -980.66,1906.62 -965.66,1921.62 JP400_PortIOD.12@-965.66,1987.37
I7_PortIOA: JP400_PortIOA.11 RA406_PortIOA.1 | length 284.9
  Top Layer w10: JP400_PortIOA.11@-2083.77,-1326.41 -2033.77,-1276.41 -1897.16,-1276.41 -1882.16,-1291.41 RA406_PortIOA.1@-1825.77,-1291.41
I7_PortIOB: JP400_PortIOB.11 RA406_PortIOB.1 | length 284.9
  Top Layer w10: RA406_PortIOB.1@799.74,-2186.91 799.74,-2243.3 784.74,-2258.3 784.74,-2394.91 JP400_PortIOB.11@834.74,-2444.91
I7_PortIOC: JP400_PortIOC.11 RA406_PortIOC.1 | length 284.9
  Top Layer w10: RA406_PortIOC.1@1795.24,538.59 1851.63,538.59 1866.63,523.59 2003.24,523.59 JP400_PortIOC.11@2053.24,573.59
I7_PortIOD: JP400_PortIOD.11 RA406_PortIOD.1 | length 284.9
  Top Layer w10: JP400_PortIOD.11@-965.66,2087.37 -915.66,2037.37 -915.66,1900.76 -930.66,1885.76 RA406_PortIOD.1@-930.66,1829.37
I8_PortIOA: JP400_PortIOA.16 RA407_PortIOA.4 | length 164.2
  Top Layer w10: JP400_PortIOA.16@-1983.77,-1126.41 -1918.02,-1126.41 -1903.02,-1141.41 RA407_PortIOA.4@-1825.77,-1141.41
I8_PortIOB: JP400_PortIOB.16 RA407_PortIOB.4 | length 164.2
  Top Layer w10: JP400_PortIOB.16@634.74,-2344.91 634.74,-2279.17 649.74,-2264.17 RA407_PortIOB.4@649.74,-2186.91
I8_PortIOC: JP400_PortIOC.16 RA407_PortIOC.4 | length 164.2
  Top Layer w10: RA407_PortIOC.4@1795.24,388.59 1872.49,388.59 1887.49,373.59 JP400_PortIOC.16@1953.24,373.59
I8_PortIOD: JP400_PortIOD.16 RA407_PortIOD.4 | length 164.2
  Top Layer w10: RA407_PortIOD.4@-780.66,1829.37 -780.66,1906.62 -765.66,1921.62 JP400_PortIOD.16@-765.66,1987.37
I9_PortIOA: JP400_PortIOA.15 RA407_PortIOA.3 | length 286.2
  Top Layer w10: JP400_PortIOA.15@-2083.77,-1126.41 -2032.19,-1074.83 -1905.03,-1074.83 -1888.45,-1091.41 RA407_PortIOA.3@-1825.77,-1091.41
I9_PortIOB: JP400_PortIOB.15 RA407_PortIOB.3 | length 286.2
  Top Layer w10: RA407_PortIOB.3@599.74,-2186.91 599.74,-2249.6 583.16,-2266.17 583.16,-2393.34 JP400_PortIOB.15@634.74,-2444.91
I9_PortIOC: JP400_PortIOC.15 RA407_PortIOC.3 | length 286.2
  Top Layer w10: RA407_PortIOC.3@1795.24,338.59 1857.93,338.59 1874.5,322.02 2001.66,322.02 JP400_PortIOC.15@2053.24,373.59
I9_PortIOD: JP400_PortIOD.15 RA407_PortIOD.3 | length 286.2
  Top Layer w10: JP400_PortIOD.15@-765.66,2087.37 -714.08,2035.8 -714.08,1908.63 -730.66,1892.06 RA407_PortIOD.3@-730.66,1829.37
I10_PortIOA: JP400_PortIOA.18 RA407_PortIOA.2 | length 164.2
  Top Layer w10: JP400_PortIOA.18@-1983.77,-1026.41 -1918.02,-1026.41 -1903.02,-1041.41 RA407_PortIOA.2@-1825.77,-1041.41
I10_PortIOB: JP400_PortIOB.18 RA407_PortIOB.2 | length 164.2
  Top Layer w10: JP400_PortIOB.18@534.74,-2344.91 534.74,-2279.17 549.74,-2264.17 RA407_PortIOB.2@549.74,-2186.91
I10_PortIOC: JP400_PortIOC.18 RA407_PortIOC.2 | length 164.2
  Top Layer w10: RA407_PortIOC.2@1795.24,288.59 1872.49,288.59 1887.49,273.59 JP400_PortIOC.18@1953.24,273.59
I10_PortIOD: JP400_PortIOD.18 RA407_PortIOD.2 | length 164.2
  Top Layer w10: RA407_PortIOD.2@-680.66,1829.37 -680.66,1906.62 -665.66,1921.62 JP400_PortIOD.18@-665.66,1987.37
I11_PortIOA: JP400_PortIOA.17 RA407_PortIOA.1 | length 284.9
  Top Layer w10: JP400_PortIOA.17@-2083.77,-1026.41 -2033.77,-976.41 -1897.16,-976.41 -1882.16,-991.41 RA407_PortIOA.1@-1825.77,-991.41
I11_PortIOB: JP400_PortIOB.17 RA407_PortIOB.1 | length 284.9
  Top Layer w10: RA407_PortIOB.1@499.74,-2186.91 499.74,-2243.3 484.74,-2258.3 484.74,-2394.91 JP400_PortIOB.17@534.74,-2444.91
I11_PortIOC: JP400_PortIOC.17 RA407_PortIOC.1 | length 284.9
  Top Layer w10: RA407_PortIOC.1@1795.24,238.59 1851.63,238.59 1866.63,223.59 2003.24,223.59 JP400_PortIOC.17@2053.24,273.59
I11_PortIOD: JP400_PortIOD.17 RA407_PortIOD.1 | length 284.9
  Top Layer w10: JP400_PortIOD.17@-665.66,2087.37 -615.66,2037.37 -615.66,1900.76 -630.66,1885.76 RA407_PortIOD.1@-630.66,1829.37
I12_PortIOA: JP400_PortIOA.22 RA400_PortIOA.4 | length 164.2
  Top Layer w10: JP400_PortIOA.22@-1983.77,-826.41 -1918.02,-826.41 -1903.02,-841.41 RA400_PortIOA.4@-1825.77,-841.41
I12_PortIOB: JP400_PortIOB.22 RA400_PortIOB.4 | length 164.2
  Top Layer w10: JP400_PortIOB.22@334.74,-2344.91 334.74,-2279.17 349.74,-2264.17 RA400_PortIOB.4@349.74,-2186.91
I12_PortIOC: JP400_PortIOC.22 RA400_PortIOC.4 | length 164.2
  Top Layer w10: RA400_PortIOC.4@1795.24,88.59 1872.49,88.59 1887.49,73.59 JP400_PortIOC.22@1953.24,73.59
I12_PortIOD: JP400_PortIOD.22 RA400_PortIOD.4 | length 164.2
  Top Layer w10: RA400_PortIOD.4@-480.66,1829.37 -480.66,1906.62 -465.66,1921.62 JP400_PortIOD.22@-465.66,1987.37
I13_PortIOA: JP400_PortIOA.21 RA400_PortIOA.3 | length 286.2
  Top Layer w10: JP400_PortIOA.21@-2083.77,-826.41 -2032.19,-774.83 -1905.03,-774.83 -1888.45,-791.41 RA400_PortIOA.3@-1825.77,-791.41
I13_PortIOB: JP400_PortIOB.21 RA400_PortIOB.3 | length 286.2
  Top Layer w10: RA400_PortIOB.3@299.74,-2186.91 299.74,-2249.6 283.16,-2266.17 283.16,-2393.34 JP400_PortIOB.21@334.74,-2444.91
I13_PortIOC: JP400_PortIOC.21 RA400_PortIOC.3 | length 286.2
  Top Layer w10: RA400_PortIOC.3@1795.24,38.59 1857.93,38.59 1874.5,22.02 2001.66,22.02 JP400_PortIOC.21@2053.24,73.59
I13_PortIOD: JP400_PortIOD.21 RA400_PortIOD.3 | length 286.2
  Top Layer w10: JP400_PortIOD.21@-465.66,2087.37 -414.08,2035.8 -414.08,1908.63 -430.66,1892.06 RA400_PortIOD.3@-430.66,1829.37
I14_PortIOA: JP400_PortIOA.24 RA400_PortIOA.2 | length 164.2
  Top Layer w10: JP400_PortIOA.24@-1983.77,-726.41 -1918.02,-726.41 -1903.02,-741.41 RA400_PortIOA.2@-1825.77,-741.41
I14_PortIOB: JP400_PortIOB.24 RA400_PortIOB.2 | length 164.2
  Top Layer w10: JP400_PortIOB.24@234.74,-2344.91 234.74,-2279.17 249.74,-2264.17 RA400_PortIOB.2@249.74,-2186.91
I14_PortIOC: JP400_PortIOC.24 RA400_PortIOC.2 | length 164.2
  Top Layer w10: RA400_PortIOC.2@1795.24,-11.41 1872.49,-11.41 1887.49,-26.41 JP400_PortIOC.24@1953.24,-26.41
I14_PortIOD: JP400_PortIOD.24 RA400_PortIOD.2 | length 164.2
  Top Layer w10: RA400_PortIOD.2@-380.66,1829.37 -380.66,1906.62 -365.66,1921.62 JP400_PortIOD.24@-365.66,1987.37
I15_PortIOA: JP400_PortIOA.23 RA400_PortIOA.1 | length 284.9
  Top Layer w10: JP400_PortIOA.23@-2083.77,-726.41 -2033.77,-676.41 -1897.16,-676.41 -1882.16,-691.41 RA400_PortIOA.1@-1825.77,-691.41
I15_PortIOB: JP400_PortIOB.23 RA400_PortIOB.1 | length 284.9
  Top Layer w10: RA400_PortIOB.1@199.74,-2186.91 199.74,-2243.3 184.74,-2258.3 184.74,-2394.91 JP400_PortIOB.23@234.74,-2444.91
I15_PortIOC: JP400_PortIOC.23 RA400_PortIOC.1 | length 284.9
  Top Layer w10: RA400_PortIOC.1@1795.24,-61.41 1851.63,-61.41 1866.63,-76.41 2003.24,-76.41 JP400_PortIOC.23@2053.24,-26.41
I15_PortIOD: JP400_PortIOD.23 RA400_PortIOD.1 | length 284.9
  Top Layer w10: JP400_PortIOD.23@-365.66,2087.37 -315.66,2037.37 -315.66,1900.76 -330.66,1885.76 RA400_PortIOD.1@-330.66,1829.37
I16_PortIOA: JP400_PortIOA.25 R402_PortIOA.2 | length 336.7
  Top Layer w10: JP400_PortIOA.25@-2083.77,-626.41 -2034.97,-577.61 -1947.34,-577.61 -1874.73,-505 R402_PortIOA.2@-1797.4,-505
I16_PortIOB: JP400_PortIOB.25 R402_PortIOB.2 | length 238.9
  Top Layer w10: R402_PortIOB.2@52.6,-2240 52.6,-2282.34 86.59,-2316.34 86.59,-2396.77 JP400_PortIOB.25@134.74,-2444.91
I16_PortIOC: JP400_PortIOC.25 R402_PortIOC.2 | length 344.1
  Top Layer w10: R402_PortIOC.2@1762.4,-255 1801.56,-255 1882.39,-174.17 2005.48,-174.17 JP400_PortIOC.25@2053.24,-126.41
I16_PortIOD: JP400_PortIOD.25 R402_PortIOD.2 | length 344.1
  Top Layer w10: JP400_PortIOD.25@-265.66,2087.37 -216.48,2038.19 -216.48,1941.43 -137.07,1862.02 R402_PortIOD.2@-137.07,1796.53
INA0: RA401_PortIOA.5 RA402_PortIOA.8 U1.154 | length 2120.5
  Top Layer w6: RA402_PortIOA.8@-1605.77,-1741.41 -1552.9,-1741.41 -1521.17,-1709.68 -1521.17,-1561.77 -1496.04,-1536.64 -1331.06,-1536.64 -1046.61,-1252.18 -1046.61,-774.04 -939.72,-667.15 -939.72,-489.05 -880.61,-429.94 -667.03,-429.94 -651.66,-445.31 U1.154@-601.88,-445.31
  Top Layer w10: RA401_PortIOA.5@-1701.77,-1741.41 RA402_PortIOA.8@-1605.77,-1741.41
INA1: RA401_PortIOA.6 RA402_PortIOA.7 U1.152 | length 2094.3
  Top Layer w6: RA402_PortIOA.7@-1605.77,-1691.41 -1561.96,-1691.41 -1536.73,-1666.18 -1536.73,-1560.36 -1501.01,-1524.64 -1337.76,-1524.64 -1058.61,-1245.49 -1058.61,-562.68 -901.87,-405.94 U1.152@-601.88,-405.94
  Top Layer w10: RA401_PortIOA.6@-1701.77,-1691.41 RA402_PortIOA.7@-1605.77,-1691.41
INA2: RA401_PortIOA.7 RA402_PortIOA.6 U1.151 | length 2058.4
  Top Layer w6: RA402_PortIOA.6@-1605.77,-1641.41 -1568.06,-1641.41 -1548.73,-1622.08 -1548.73,-1555.39 -1505.37,-1512.03 -1342.87,-1512.03 -1070.61,-1239.77 -1070.61,-557.71 -906.84,-393.94 -662.78,-393.94 -655.09,-386.25 U1.151@-601.88,-386.25
  Top Layer w10: RA401_PortIOA.7@-1701.77,-1641.41 RA402_PortIOA.6@-1605.77,-1641.41
INA3: RA401_PortIOA.8 RA402_PortIOA.5 U1.150 | length 2024.2
  Top Layer w6: RA402_PortIOA.5@-1605.77,-1591.41 -1571.21,-1591.41 -1561.52,-1581.72 -1561.52,-1551.21 -1510.34,-1500.03 -1348.58,-1500.03 -1082.61,-1234.06 -1082.61,-552.74 -911.81,-381.94 -667.78,-381.94 -652.41,-366.57 U1.150@-601.88,-366.57
  Top Layer w10: RA401_PortIOA.8@-1701.77,-1591.41 RA402_PortIOA.5@-1605.77,-1591.41
INA4: RA404_PortIOA.8 RA406_PortIOA.5 U1.149 | length 1868
  Top Layer w6: RA404_PortIOA.8@-1605.77,-1441.41 -1552.9,-1441.41 -1521.17,-1409.68 -1521.17,-1261.77 -1496.04,-1236.64 -1394.16,-1236.64 -1094.61,-937.09 -1094.61,-547.77 -915.39,-368.55 -671.39,-368.55 -649.72,-346.88 U1.149@-601.88,-346.88
  Top Layer w10: RA406_PortIOA.5@-1701.77,-1441.41 RA404_PortIOA.8@-1605.77,-1441.41
INA5: RA404_PortIOA.7 RA406_PortIOA.6 U1.148 | length 1830.3
  Top Layer w6: RA404_PortIOA.7@-1605.77,-1391.41 -1561.96,-1391.41 -1536.73,-1366.18 -1536.73,-1260.36 -1501.01,-1224.64 -1399.87,-1224.64 -1106.61,-931.37 -1106.61,-542.8 -918.36,-354.55 -674.39,-354.55 -647.04,-327.2 U1.148@-601.88,-327.2
  Top Layer w10: RA406_PortIOA.6@-1701.77,-1391.41 RA404_PortIOA.7@-1605.77,-1391.41
INA6: RA404_PortIOA.6 RA406_PortIOA.7 U1.147 | length 1794.8
  Top Layer w6: RA404_PortIOA.6@-1605.77,-1341.41 -1568.06,-1341.41 -1548.73,-1322.08 -1548.73,-1255.39 -1505.37,-1212.03 -1405.02,-1212.03 -1118.61,-925.62 -1118.61,-537.08 -924.08,-342.55 -679.39,-342.55 -644.35,-307.51 U1.147@-601.88,-307.51
  Top Layer w10: RA406_PortIOA.7@-1701.77,-1341.41 RA404_PortIOA.6@-1605.77,-1341.41
INA7: RA404_PortIOA.5 RA406_PortIOA.8 U1.146 | length 1761.1
  Top Layer w6: RA404_PortIOA.5@-1605.77,-1291.41 -1571.21,-1291.41 -1561.52,-1281.72 -1561.52,-1251.21 -1510.34,-1200.03 -1409.99,-1200.03 -1130.61,-920.65 -1130.61,-532.11 -927.05,-328.55 -682.39,-328.55 -641.67,-287.83 U1.146@-601.88,-287.83
  Top Layer w10: RA406_PortIOA.8@-1701.77,-1291.41 RA404_PortIOA.5@-1605.77,-1291.41
INA8: RA403_PortIOA.8 RA407_PortIOA.5 U1.145 | length 1670
  Top Layer w6: RA403_PortIOA.8@-1605.77,-1141.41 -1552.9,-1141.41 -1521.17,-1109.68 -1521.17,-961.77 -1496.04,-936.64 -1344.19,-936.64 -1280.11,-872.56 -1280.11,-664.64 -932.02,-316.55 -687.39,-316.55 -638.98,-268.14 U1.145@-601.88,-268.14
  Top Layer w10: RA407_PortIOA.5@-1703.23,-1139.48 RA403_PortIOA.8@-1607.23,-1139.48
INA9: RA403_PortIOA.7 RA407_PortIOA.6 U1.141 | length 1756.2
  Top Layer w6: RA403_PortIOA.7@-1605.77,-1091.41 -1561.96,-1091.41 -1536.73,-1066.18 -1536.73,-960.36 -1501.01,-924.64 -1349.16,-924.64 -1292.11,-867.59 -1292.11,-658.33 -930.81,-297.03 -930.81,-188.79 -889.57,-147.55 -684.39,-147.55 -642.54,-189.4 U1.141@-601.88,-189.4
  Top Layer w10: RA407_PortIOA.6@-1703.23,-1089.48 RA403_PortIOA.7@-1607.23,-1089.48
INA10: RA403_PortIOA.6 RA407_PortIOA.7 U1.140 | length 1714.7
  Top Layer w6: RA403_PortIOA.6@-1605.77,-1041.41 -1568.06,-1041.41 -1548.73,-1022.08 -1548.73,-955.39 -1505.37,-912.03 -1353.53,-912.03 -1304.11,-862.61 -1304.11,-653.36 -943.18,-292.43 -943.18,-183.44 -895.28,-135.55 -679.42,-135.55 -645.25,-169.72 U1.140@-601.88,-169.72
  Top Layer w10: RA407_PortIOA.7@-1703.23,-1039.48 RA403_PortIOA.6@-1607.23,-1039.48
INA11: RA403_PortIOA.5 RA407_PortIOA.8 U1.139 | length 1675.6
  Top Layer w6: RA403_PortIOA.5@-1605.77,-991.41 -1571.21,-991.41 -1561.52,-981.72 -1561.52,-951.21 -1510.34,-900.03 -1358.5,-900.03 -1316.11,-857.64 -1316.11,-647.89 -955.18,-286.96 -955.18,-176.75 -901.98,-123.55 -674.45,-123.55 -647.97,-150.03 U1.139@-601.88,-150.03
  Top Layer w10: RA407_PortIOA.8@-1703.23,-989.48 RA403_PortIOA.5@-1607.23,-989.48
INA12: RA400_PortIOA.5 RA405_PortIOA.8 U1.138 | length 1561.6
  Top Layer w6: RA405_PortIOA.8@-1605.77,-841.41 -1552.9,-841.41 -1521.17,-809.68 -1521.17,-661.77 -1496.04,-636.64 -1321.83,-636.64 -967.78,-282.59 -967.78,-171.64 -907.69,-111.55 -669.48,-111.55 -650.68,-130.35 U1.138@-601.88,-130.35
  Top Layer w10: RA400_PortIOA.5@-1701.77,-841.41 RA405_PortIOA.8@-1605.77,-841.41
INA13: RA400_PortIOA.6 RA405_PortIOA.7 U1.136 | length 1517.4
  Top Layer w6: RA405_PortIOA.7@-1605.77,-791.41 -1561.96,-791.41 -1536.73,-766.18 -1536.73,-660.36 -1501.01,-624.64 -1326.8,-624.64 -979.78,-277.62 -979.78,-165.92 -913.4,-99.55 -658.51,-99.55 -649.93,-90.98 U1.136@-601.88,-90.98
  Top Layer w10: RA400_PortIOA.6@-1701.77,-791.41 RA405_PortIOA.7@-1605.77,-791.41
INA14: RA400_PortIOA.7 RA405_PortIOA.6 U1.135 | length 1482.4
  Top Layer w6: RA405_PortIOA.6@-1605.77,-741.41 -1568.06,-741.41 -1548.73,-722.08 -1548.73,-655.39 -1505.37,-612.03 -1331.16,-612.03 -992.38,-273.24 -992.38,-160.81 -919.11,-87.55 -663.48,-87.55 -647.22,-71.29 U1.135@-601.88,-71.29
  Top Layer w10: RA400_PortIOA.7@-1701.77,-741.41 RA405_PortIOA.6@-1605.77,-741.41
INA15: RA400_PortIOA.8 RA405_PortIOA.5 U1.134 | length 1449.1
  Top Layer w6: RA405_PortIOA.5@-1605.77,-691.41 -1571.21,-691.41 -1561.52,-681.72 -1561.52,-651.21 -1510.34,-600.03 -1336.13,-600.03 -1004.38,-268.27 -1004.38,-155.1 -924.83,-75.55 -668.45,-75.55 -644.5,-51.61 U1.134@-601.88,-51.61
  Top Layer w10: RA400_PortIOA.8@-1701.77,-691.41 RA405_PortIOA.5@-1605.77,-691.41
INA16: R401_PortIOA.2 R402_PortIOA.1 U1.133 | length 1468.4
  Top Layer w6: R401_PortIOA.2@-1722.6,-590 R402_PortIOA.1@-1722.6,-505 -1258.07,-505 -1016.47,-263.4 -1016.47,-149.57 -930.45,-63.55 -673.42,-63.55 -641.79,-31.92 U1.133@-601.88,-31.92
INB0: RA401_PortIOB.5 RA402_PortIOB.8 U1.206 | length 1915
  Top Layer w6: U1.206@447.33,-569.32 447.33,-619.11 431.96,-634.48 431.96,-810.46 452.26,-830.76 452.26,-1164.08 483.1,-1194.92 1050.68,-1762.51 1050.68,-1855.02 1080.36,-1884.7 1210.55,-1884.7 1249.74,-1923.89 RA402_PortIOB.8@1249.74,-1966.91
  Top Layer w10: RA401_PortIOB.5@1248.59,-2061.77 RA402_PortIOB.8@1248.59,-1965.77
INB1: RA401_PortIOB.6 RA402_PortIOB.7 U1.205 | length 1875.4
  Top Layer w6: U1.205@427.65,-569.32 427.65,-621.82 419.96,-629.51 419.96,-817.35 439.46,-836.85 439.46,-1168.25 1037.89,-1766.68 1037.89,-1859.2 1075.39,-1896.7 1170.38,-1896.7 1199.74,-1926.05 RA402_PortIOB.7@1199.74,-1966.91
  Top Layer w10: RA401_PortIOB.6@1198.59,-2061.77 RA402_PortIOB.7@1198.59,-1965.77
INB2: RA401_PortIOB.7 RA402_PortIOB.6 U1.204 | length 1836.4
  Top Layer w6: U1.204@407.96,-569.32 407.96,-822.32 426.66,-841.03 426.66,-1172.43 1025.09,-1770.86 1025.09,-1863.38 1070.42,-1908.7 1131.2,-1908.7 1149.74,-1927.24 RA402_PortIOB.6@1149.74,-1966.91
  Top Layer w10: RA401_PortIOB.7@1148.59,-2061.77 RA402_PortIOB.6@1148.59,-1965.77
INB3: RA401_PortIOB.8 RA402_PortIOB.5 U1.203 | length 1802.1
  Top Layer w6: U1.203@388.28,-569.32 388.28,-622.54 395.96,-630.22 395.96,-827.3 412.89,-844.22 412.89,-1175.62 1012.29,-1775.03 1012.29,-1867.55 1065.44,-1920.7 1089.07,-1920.7 1099.74,-1931.37 RA402_PortIOB.5@1099.74,-1966.91
  Top Layer w10: RA401_PortIOB.8@1098.59,-2061.77 RA402_PortIOB.5@1098.59,-1965.77
INB4: RA404_PortIOB.8 RA406_PortIOB.5 U1.202 | length 1821.4
  Top Layer w6: U1.202@368.59,-569.32 368.59,-619.85 383.96,-635.22 383.96,-832.27 400.09,-848.39 400.09,-1444.08 752.45,-1796.45 752.45,-1874.44 762.11,-1884.09 910.73,-1884.09 949.74,-1923.1 RA404_PortIOB.8@949.74,-1966.91
  Top Layer w10: RA406_PortIOB.5@948.59,-2061.77 RA404_PortIOB.8@948.59,-1965.77
INB5: RA404_PortIOB.7 RA406_PortIOB.6 U1.201 | length 1793.5
  Top Layer w6: U1.201@348.91,-569.32 348.91,-617.17 370.58,-638.83 370.58,-836.07 388.09,-853.58 388.09,-1449.05 739.85,-1800.81 739.85,-1886.95 748.99,-1896.09 871.55,-1896.09 899.74,-1924.28 RA404_PortIOB.7@899.74,-1966.91
  Top Layer w10: RA406_PortIOB.6@898.59,-2061.77 RA404_PortIOB.7@898.59,-1965.77
INB6: RA404_PortIOB.6 RA406_PortIOB.7 U1.200 | length 1758.1
  Top Layer w6: U1.200@329.22,-569.32 329.22,-614.48 356.58,-641.83 356.58,-839.79 376.09,-859.3 376.09,-1454.53 727.85,-1806.29 727.85,-1891.92 744.63,-1908.7 828.05,-1908.7 849.74,-1930.38 RA404_PortIOB.6@849.74,-1966.91
  Top Layer w10: RA406_PortIOB.7@848.59,-2061.77 RA404_PortIOB.6@848.59,-1965.77
INB7: RA404_PortIOB.5 RA406_PortIOB.8 U1.199 | length 1722
  Top Layer w6: U1.199@309.54,-569.32 309.54,-611.8 344.58,-646.83 344.58,-845.5 364.09,-865.02 364.09,-1459.5 715.05,-1810.46 715.05,-1896.09 739.66,-1920.7 782.96,-1920.7 799.74,-1937.47 RA404_PortIOB.5@799.74,-1966.91
  Top Layer w10: RA406_PortIOB.8@798.59,-2061.77 RA404_PortIOB.5@798.59,-1965.77
INB8: RA403_PortIOB.8 RA407_PortIOB.5 U1.198 | length 1722
  Top Layer w6: U1.198@289.85,-569.32 289.85,-609.11 330.58,-649.83 330.58,-848.47 351.86,-869.76 351.86,-1634.55 447.52,-1730.21 464.45,-1747.14 464.45,-1871.49 478.22,-1885.27 613.67,-1885.27 649.74,-1921.33 RA403_PortIOB.8@649.74,-1966.91
  Top Layer w10: RA407_PortIOB.5@648.59,-2061.77 RA403_PortIOB.8@648.59,-1965.77
INB9: RA403_PortIOB.7 RA407_PortIOB.6 U1.194 | length 1745.5
  Top Layer w6: U1.194@211.11,-569.32 211.11,-606.43 167.58,-649.96 167.58,-1008.85 256.35,-1097.62 256.35,-1556.01 435.52,-1735.18 452.45,-1752.11 452.45,-1876.83 479.21,-1903.59 572.94,-1903.59 599.74,-1930.38 RA403_PortIOB.7@599.74,-1966.91
  Top Layer w10: RA407_PortIOB.6@598.59,-2061.77 RA403_PortIOB.7@598.59,-1965.77
INB10: RA403_PortIOB.6 RA407_PortIOB.7 U1.193 | length 1706.5
  Top Layer w6: U1.193@191.43,-569.32 191.43,-609.11 155.58,-644.96 155.58,-1013.82 244.35,-1102.59 244.35,-1560.98 422.73,-1739.36 440.45,-1757.08 440.45,-1882.73 473.3,-1915.59 532.78,-1915.59 549.74,-1932.55 RA403_PortIOB.6@549.74,-1966.91
  Top Layer w10: RA407_PortIOB.7@548.59,-2061.77 RA403_PortIOB.6@548.59,-1965.77
INB11: RA403_PortIOB.5 RA407_PortIOB.8 U1.192 | length 1667
  Top Layer w6: U1.192@171.74,-569.32 171.74,-611.8 143.58,-639.96 143.58,-1018.79 232.35,-1107.56 232.35,-1565.95 410.12,-1743.72 428.45,-1762.05 428.45,-1888.64 467.4,-1927.59 491.63,-1927.59 499.74,-1935.7 RA403_PortIOB.5@499.74,-1966.91
  Top Layer w10: RA407_PortIOB.8@498.59,-2061.77 RA403_PortIOB.5@498.59,-1965.77
INB12: RA400_PortIOB.5 RA405_PortIOB.8 U1.191 | length 1647.7
  Top Layer w6: U1.191@152.06,-569.32 152.06,-612.35 131.58,-632.83 131.58,-1023.76 220.35,-1112.53 220.35,-1571.43 398.12,-1749.2 416.45,-1767.53 416.45,-1868.82 349.74,-1935.53 RA405_PortIOB.8@349.74,-1966.91
  Top Layer w10: RA400_PortIOB.5@348.59,-2061.77 RA405_PortIOB.8@348.59,-1965.77
INB13: RA400_PortIOB.6 RA405_PortIOB.7 U1.189 | length 1677.2
  Top Layer w6: U1.189@112.69,-569.32 112.69,-614.94 119.58,-621.83 119.58,-1028.73 208.35,-1117.5 208.35,-1576.4 385.33,-1753.38 404.45,-1772.5 404.45,-1863.84 349.56,-1918.73 316.47,-1918.73 299.74,-1935.46 RA405_PortIOB.7@299.74,-1966.91
  Top Layer w10: RA400_PortIOB.6@298.59,-2061.77 RA405_PortIOB.7@298.59,-1965.77
INB14: RA400_PortIOB.7 RA405_PortIOB.6 U1.188 | length 1717.6
  Top Layer w6: U1.188@93,-569.32 93.01,-619.11 107.58,-633.68 107.58,-1033.7 196.35,-1122.47 196.35,-1581.37 392.45,-1777.47 392.45,-1858.87 345.31,-1906.01 275.49,-1906.01 249.74,-1931.76 RA405_PortIOB.6@249.74,-1966.91
  Top Layer w10: RA400_PortIOB.7@248.59,-2061.77 RA405_PortIOB.6@248.59,-1965.77
INB15: RA400_PortIOB.8 RA405_PortIOB.5 U1.187 | length 1559.6
  Top Layer w6: U1.187@73.32,-569.32 73.32,-616.39 95.58,-638.65 95.58,-1040.4 183.81,-1128.64 183.81,-1763.94 169.25,-1778.51 169.25,-1894.2 199.74,-1924.69 RA405_PortIOB.5@199.74,-1966.91 RA405_PortIOB.5@198.59,-1965.77
  Top Layer w10: RA400_PortIOB.8@198.59,-2061.77 RA405_PortIOB.5@198.59,-1965.77
INB16: R401_PortIOB.2 R402_PortIOB.1 U1.185 | length 1964.6
  Top Layer w6: U1.185@33.95,-569.32 33.95,-634.19 15.74,-652.39 15.74,-868.74 83.58,-936.58 83.58,-1045.93 171.81,-1134.17 171.81,-1758.97 156.46,-1774.33 156.46,-1993.58 166.3,-2003.42 166.3,-2197.27 127.4,-2236.17 R402_PortIOB.1@127.4,-2240
  Top Layer w10: R401_PortIOB.2@-22.6,-2240 -22.6,-2231.68 20.66,-2188.42 81.67,-2188.42 R402_PortIOB.1@127.4,-2234.15
INC0: RA401_PortIOC.5 RA402_PortIOC.8 U1.48 | length 1413.6
  Top Layer w6: U1.48@571.35,440.52 785.92,440.52 1129.22,783.82 1465.51,783.82 1490.64,808.95 1490.64,956.86 1522.37,988.59 RA402_PortIOC.8@1575.24,988.59
  Top Layer w10: RA402_PortIOC.8@1575.24,987.45 RA401_PortIOC.5@1671.24,987.45
INC1: RA401_PortIOC.6 RA402_PortIOC.7 U1.47 | length 1376.3
  Top Layer w6: U1.47@571.35,420.84 783.2,420.84 1134.19,771.82 1470.48,771.82 1506.2,807.54 1506.2,913.36 1531.43,938.59 RA402_PortIOC.7@1575.24,938.59
  Top Layer w10: RA402_PortIOC.7@1575.24,937.45 RA401_PortIOC.6@1671.24,937.45
INC2: RA401_PortIOC.7 RA402_PortIOC.6 U1.46 | length 1340.9
  Top Layer w6: U1.46@571.35,401.15 624.56,401.15 632.25,408.83 788.17,408.83 1138.55,759.21 1474.84,759.21 1518.2,802.57 1518.2,869.26 1537.53,888.59 RA402_PortIOC.6@1575.24,888.59
  Top Layer w10: RA402_PortIOC.6@1575.24,887.45 RA401_PortIOC.7@1671.24,887.45
INC3: RA401_PortIOC.8 RA402_PortIOC.5 U1.45 | length 1307.1
  Top Layer w6: U1.45@571.35,381.47 621.88,381.46 637.25,396.83 793.14,396.83 1143.52,747.21 1479.81,747.21 1531,798.39 1531,828.91 1540.68,838.59 RA402_PortIOC.5@1575.24,838.59
  Top Layer w10: RA402_PortIOC.5@1575.24,837.45 RA401_PortIOC.8@1671.24,837.45
INC4: RA404_PortIOC.8 RA406_PortIOC.5 U1.44 | length 1321.9
  Top Layer w6: U1.44@571.35,361.78 619.19,361.78 640.86,383.45 966.05,383.45 1066.42,483.82 1465.51,483.82 1490.64,508.95 1490.64,656.86 1522.37,688.59 RA404_PortIOC.8@1575.24,688.59
  Top Layer w10: RA404_PortIOC.8@1574.1,687.45 RA406_PortIOC.5@1670.1,687.45
INC5: RA404_PortIOC.7 RA406_PortIOC.6 U1.43 | length 1284.7
  Top Layer w6: U1.43@571.35,342.1 616.51,342.09 643.86,369.45 969.02,369.45 1071.39,471.82 1470.48,471.82 1506.2,507.54 1506.2,613.36 1531.43,638.59 RA404_PortIOC.7@1575.24,638.59
  Top Layer w10: RA404_PortIOC.7@1574.1,637.45 RA406_PortIOC.6@1670.1,637.45
INC6: RA404_PortIOC.6 RA406_PortIOC.7 U1.42 | length 1249.2
  Top Layer w6: U1.42@571.35,322.41 613.82,322.41 648.86,357.45 973.99,357.45 1075.76,459.21 1474.84,459.21 1518.2,502.57 1518.2,569.26 1537.53,588.59 RA404_PortIOC.6@1575.24,588.59
  Top Layer w10: RA404_PortIOC.6@1574.1,587.45 RA406_PortIOC.7@1670.1,587.45
INC7: RA404_PortIOC.5 RA406_PortIOC.8 U1.41 | length 1215.5
  Top Layer w6: U1.41@571.35,302.73 611.14,302.72 651.86,343.45 976.96,343.45 1080.73,447.21 1479.81,447.21 1531,498.39 1531,528.91 1540.68,538.59 RA404_PortIOC.5@1575.24,538.59
  Top Layer w10: RA404_PortIOC.5@1574.1,537.45 RA406_PortIOC.8@1670.1,537.45
INC8: RA403_PortIOC.8 RA407_PortIOC.5 U1.40 | length 1175.2
  Top Layer w6: U1.40@571.35,283.04 608.45,283.04 656.86,331.45 981.93,331.45 1077.22,426.74 1497.77,426.74 1535.92,388.59 RA403_PortIOC.8@1575.24,388.59
  Top Layer w10: RA403_PortIOC.8@1574.1,387.45 RA407_PortIOC.5@1670.1,387.45
INC9: RA403_PortIOC.7 RA407_PortIOC.6 U1.36 | length 1253.6
  Top Layer w6: U1.36@571.35,204.3 608.45,204.3 651.99,160.77 1459.43,160.77 1506.2,207.54 1506.2,313.36 1531.43,338.59 RA403_PortIOC.7@1575.24,338.59
  Top Layer w10: RA403_PortIOC.7@1574.1,337.45 RA407_PortIOC.6@1670.1,337.45
INC10: RA403_PortIOC.6 RA407_PortIOC.7 U1.35 | length 1211.7
  Top Layer w6: U1.35@571.35,184.61 611.14,184.61 646.99,148.77 1464.4,148.77 1518.2,202.57 1518.2,269.26 1537.53,288.59 RA403_PortIOC.6@1575.24,288.59
  Top Layer w10: RA403_PortIOC.6@1574.1,287.45 RA407_PortIOC.7@1670.1,287.45
INC11: RA403_PortIOC.5 RA407_PortIOC.8 U1.34 | length 1171.6
  Top Layer w6: U1.34@571.35,164.93 613.82,164.93 641.99,136.77 1469.37,136.77 1531,198.39 1531,228.91 1540.68,238.59 RA403_PortIOC.5@1575.24,238.59
  Top Layer w10: RA403_PortIOC.5@1574.1,237.45 RA407_PortIOC.8@1670.1,237.45
INC12: RA400_PortIOC.5 RA405_PortIOC.8 U1.33 | length 1123.4
  Top Layer w6: U1.33@571.35,145.24 614.38,145.25 634.86,124.77 1486.2,124.77 1522.37,88.59 RA405_PortIOC.8@1575.24,88.59
  Top Layer w10: RA405_PortIOC.8@1574.1,87.45 RA400_PortIOC.5@1670.1,87.45
INC13: RA400_PortIOC.6 RA405_PortIOC.7 U1.31 | length 1316.7
  Top Layer w6: U1.31@571.35,105.87 616.97,105.88 623.86,112.77 1185.52,112.77 1406,-107.71 1490.95,-107.71 1506.2,-92.46 1506.2,13.36 1531.43,38.59 RA405_PortIOC.7@1575.24,38.59
  Top Layer w10: RA405_PortIOC.7@1574.1,37.45 RA400_PortIOC.6@1670.1,37.45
